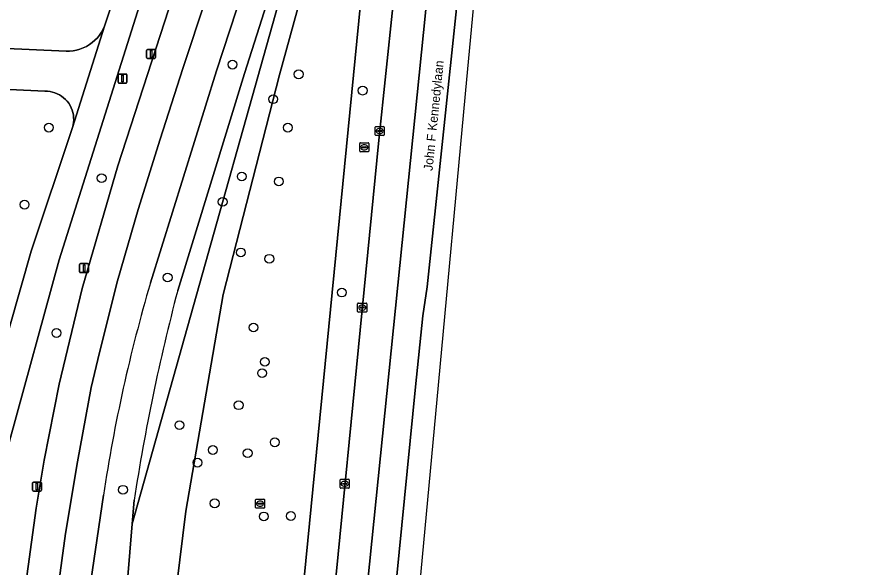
# Model space of a CAD drawing. Extents: x 161354 to 162026, y 386504 to 387460.
# Drawn here: x 161888.6 to 161983.7, y 386581.5 to 386642.5 of the extents above; entities that cross this region are included whole.
import ezdxf

# ---------------------------------------------------------------- set-up
doc = ezdxf.new("R2010")
doc.units = 0
for name, color, linetype in [('IMGEO_Berm_groen', 7, 'Continuous'), ('IMGEO_Boom', 7, 'Continuous'), ('IMGEO_Fietspad_gesloten', 7, 'Continuous'), ('IMGEO_Fietspad_open', 7, 'Continuous'), ('IMGEO_Groenvoorziening', 7, 'Continuous'), ('IMGEO_Kolk', 7, 'Continuous'), ('IMGEO_Lichtmast', 7, 'Continuous'), ('IMGEO_Loofbos', 7, 'Continuous'), ('IMGEO_Openbare_ruimte_label', 7, 'Continuous'), ('IMGEO_Rijbaan_regionaal_gesloten', 7, 'Continuous'), ('IMGEO_Rioolput', 7, 'Continuous'), ('IMGEO_Verkeersbordpaal', 7, 'Continuous')]:
    doc.layers.add(name, color=color, linetype=linetype)

msp = doc.modelspace()

# ---------------------------------------------------------------- linework, layer by layer
at = {"layer": 'IMGEO_Berm_groen'}
for points in [[(161934.511, 386701.688), (161935.18, 386707.852), (161935.602, 386701.48), (161931.177, 386682.181), (161926.052, 386665.823), (161928.732, 386665.815), (161932.494, 386665.803), (161936.118, 386700.366), (161937.946, 386716.259), (161935.283, 386716.755), (161932.789, 386707.078), (161930.115, 386698.021), (161925.994, 386683.412), (161910.651, 386636.523), (161903.327, 386613.063)], [(161923.643, 386665.83), (161926.052, 386665.823), (161931.177, 386682.181), (161935.602, 386701.48), (161935.18, 386707.852), (161934.511, 386701.688), (161928.819, 386682.727), (161921.08, 386659.304), (161913.742, 386636.257), (161906.341, 386612.212)], [(161906.341, 386612.212), (161913.742, 386636.257), (161921.08, 386659.304), (161928.819, 386682.727), (161934.511, 386701.688)], [(161901.521, 386589.008), (161901.303, 386586.383), (161923.643, 386665.83)], [(161898.125, 386589.557), (161896.34, 386577.532), (161895.193, 386564.876), (161893.103, 386537.735), (161892.934, 386535.989), (161898.185, 386535.127), (161902.766, 386534.908), (161902.789, 386535.354), (161903.229, 386539.182)], [(161899.074, 386555.691), (161899.477, 386564.438), (161899.737, 386567.556), (161901.303, 386586.383), (161901.521, 386589.008)]]:
    msp.add_lwpolyline(points, dxfattribs=at)
msp.add_lwpolyline([(161928.621, 386628.856), (161932.494, 386665.803), (161928.732, 386665.815), (161918.981, 386566.485), (161916.049, 386536.616), (161919.659, 386536.352), (161921.651, 386557.858)], close=True, dxfattribs=at)
for centre, radius, start, end in [((162069.828, 386563.887), 173.612, 163.54548, 171.49707), ((162122.974, 386555.11), 224.032, 165.2333, 171.29719), ((162122.974, 386555.11), 224.032, 165.2333, 171.29719)]:
    msp.add_arc(centre, radius, start, end, dxfattribs=at)
at = {"layer": 'IMGEO_Boom'}
for centre in [(161912.419, 386637.227), (161919.748, 386636.155), (161926.827, 386634.35), (161916.923, 386633.393), (161892.074, 386630.252), (161918.547, 386630.249), (161897.915, 386624.658), (161913.442, 386624.843), (161917.546, 386624.293), (161911.329, 386622.037), (161889.382, 386621.726), (161913.342, 386616.435), (161916.495, 386615.734), (161905.226, 386613.661), (161924.523, 386611.993), (161914.743, 386608.127), (161892.913, 386607.518), (161915.995, 386604.323), (161915.694, 386603.071), (161913.092, 386599.518), (161906.535, 386597.316), (161917.096, 386595.414), (161910.239, 386594.563), (161914.093, 386594.213), (161908.537, 386593.162), (161900.282, 386590.159), (161910.439, 386588.657), (161915.882, 386587.206), (161918.885, 386587.256)]:
    msp.add_circle(centre, 0.489, dxfattribs=at)
at = {"layer": 'IMGEO_Fietspad_gesloten'}
msp.add_lwpolyline([(161903.78, 386658.264), (161898.226, 386641.486), (161894.696, 386630.28), (161890.098, 386616.576), (161885.355, 386599.961), (161882.558, 386589.231), (161881.132, 386582.855), (161879.125, 386572.213), (161878.21, 386566.397), (161877.566, 386561.139), (161876.722, 386553.592), (161875.362, 386541.23), (161878.389, 386540.917), (161879.568, 386550.833), (161881.557, 386565.903), (161884.4, 386581.575), (161887.702, 386595.552), (161893.216, 386615.601), (161906.984, 386659.234)], dxfattribs=at)
at = {"layer": 'IMGEO_Fietspad_open'}
msp.add_lwpolyline([(161884.529, 386634.627), (161891.633, 386634.278), (161891.647, 386634.278), (161891.925, 386634.271), (161892.202, 386634.24), (161892.475, 386634.183), (161892.741, 386634.103), (161893, 386633.999), (161893.248, 386633.872), (161893.484, 386633.724), (161893.705, 386633.555), (161893.911, 386633.367), (161894.099, 386633.162), (161894.268, 386632.94), (161894.416, 386632.705), (161894.543, 386632.457), (161894.647, 386632.198), (161894.728, 386631.932), (161894.784, 386631.659), (161894.816, 386631.382), (161894.823, 386631.104), (161894.806, 386630.826), (161894.763, 386630.55), (161894.696, 386630.28), (161898.226, 386641.486), (161898.087, 386641.167), (161897.901, 386640.825), (161897.686, 386640.501), (161897.443, 386640.198), (161897.174, 386639.917), (161896.881, 386639.662), (161896.566, 386639.434), (161896.232, 386639.235), (161895.881, 386639.067), (161895.517, 386638.93), (161895.143, 386638.827), (161894.76, 386638.757), (161894.373, 386638.722), (161893.984, 386638.722), (161866.028, 386639.958)], dxfattribs=at)
at = {"layer": 'IMGEO_Groenvoorziening'}
for points in [[(161867.65, 386683.374), (161866.028, 386639.958), (161893.984, 386638.722), (161894.373, 386638.722), (161894.76, 386638.757), (161895.143, 386638.827), (161895.517, 386638.93), (161895.881, 386639.067), (161896.232, 386639.235), (161896.566, 386639.434), (161896.881, 386639.662), (161897.174, 386639.917), (161897.443, 386640.198), (161897.686, 386640.501), (161897.901, 386640.825), (161898.087, 386641.167), (161898.226, 386641.486), (161903.78, 386658.264)], [(161906.984, 386659.234), (161893.216, 386615.601), (161887.702, 386595.552), (161884.4, 386581.575), (161881.557, 386565.903), (161879.568, 386550.833), (161878.389, 386540.917), (161878.324, 386540.366), (161878.164, 386538.17)], [(161889.275, 386577.885), (161890.665, 386588.111), (161891.564, 386593.422), (161893.225, 386601.834), (161895.753, 386612.458), (161899.719, 386626.02), (161908.177, 386652.077), (161908.3, 386652.279)]]:
    msp.add_lwpolyline(points, dxfattribs=at)
for points in [[(161905.451, 386567.238), (161905.601, 386574.31), (161907.235, 386587.793), (161911.368, 386611.768), (161917.62, 386636.107), (161923.898, 386658.946), (161926.052, 386665.823), (161923.643, 386665.83), (161901.303, 386586.383), (161899.737, 386567.556)], [(161928.732, 386665.815), (161926.052, 386665.823), (161923.898, 386658.946), (161917.62, 386636.107), (161911.368, 386611.768), (161907.235, 386587.793), (161905.601, 386574.31), (161905.451, 386567.238), (161918.981, 386566.485)]]:
    msp.add_lwpolyline(points, close=True, dxfattribs=at)
at = {"layer": 'IMGEO_Kolk'}
for p, q in [((161928.223, 386629.45), (161928.223, 386630.302)), ((161928.298, 386630.376), (161929.15, 386630.376)), ((161928.525, 386629.919), (161928.923, 386629.919)), ((161928.711, 386630.156), (161928.736, 386630.156)), ((161929.224, 386630.302), (161929.224, 386629.45)), ((161929.15, 386629.376), (161928.298, 386629.376)), ((161928.482, 386629.87), (161928.482, 386629.882)), ((161928.92, 386629.833), (161928.522, 386629.833)), ((161928.734, 386629.596), (161928.709, 386629.596)), ((161928.966, 386629.882), (161928.966, 386629.87)), ((161926.278, 386609.9), (161926.278, 386610.752)), ((161926.353, 386610.826), (161927.205, 386610.826)), ((161926.537, 386610.32), (161926.537, 386610.332)), ((161926.975, 386610.283), (161926.577, 386610.283)), ((161926.58, 386610.369), (161926.978, 386610.369)), ((161926.789, 386610.046), (161926.764, 386610.046)), ((161926.766, 386610.606), (161926.791, 386610.606)), ((161927.021, 386610.332), (161927.021, 386610.32)), ((161927.279, 386610.752), (161927.279, 386609.9)), ((161927.205, 386609.826), (161926.353, 386609.826)), ((161924.349, 386590.397), (161924.349, 386591.249)), ((161924.424, 386591.323), (161925.276, 386591.323)), ((161924.837, 386591.103), (161924.862, 386591.103)), ((161925.35, 386591.249), (161925.35, 386590.397)), ((161925.276, 386590.323), (161924.424, 386590.323)), ((161924.608, 386590.817), (161924.608, 386590.829)), ((161925.046, 386590.78), (161924.648, 386590.78)), ((161924.651, 386590.866), (161925.049, 386590.866)), ((161924.86, 386590.543), (161924.835, 386590.543)), ((161925.092, 386590.829), (161925.092, 386590.817))]:
    msp.add_line(p, q, dxfattribs=at)
for points in [[(161928.223, 386629.45), (161928.223, 386630.302)], [(161928.298, 386630.376), (161929.15, 386630.376)], [(161929.224, 386630.302), (161929.224, 386629.45)], [(161929.15, 386629.376), (161928.298, 386629.376)], [(161926.278, 386609.9), (161926.278, 386610.752)], [(161926.353, 386610.826), (161927.205, 386610.826)], [(161927.279, 386610.752), (161927.279, 386609.9)], [(161927.205, 386609.826), (161926.353, 386609.826)], [(161924.349, 386590.397), (161924.349, 386591.249)], [(161924.424, 386591.323), (161925.276, 386591.323)], [(161925.35, 386591.249), (161925.35, 386590.397)], [(161925.276, 386590.323), (161924.424, 386590.323)]]:
    msp.add_lwpolyline(points, dxfattribs=at)
for centre, radius, start, end in [((161928.3, 386630.3), 0.0765, 91.55205, 178.44795), ((161928.3, 386630.3), 0.0765, 91.55205, 178.44795), ((161928.522, 386629.879), 0.0403, 85.87752, 175.75265), ((161928.927, 386629.881), 0.0386, 1.73085, 96.63898), ((161929.148, 386630.3), 0.0765, 1.55205, 88.44795), ((161929.148, 386630.3), 0.0765, 1.55205, 88.44795), ((161928.3, 386629.452), 0.0765, 181.55205, 268.44795), ((161928.3, 386629.452), 0.0765, 181.55205, 268.44795), ((161928.519, 386629.869), 0.0366, 178.93798, 274.71019), ((161928.923, 386629.876), 0.043, 264.86636, 352.45326), ((161929.148, 386629.452), 0.0765, 271.55205, 358.44795), ((161929.148, 386629.452), 0.0765, 271.55205, 358.44795), ((161926.355, 386610.75), 0.0765, 91.55205, 178.44795), ((161926.355, 386610.75), 0.0765, 91.55205, 178.44795), ((161926.577, 386610.329), 0.0403, 85.87752, 175.75265), ((161926.574, 386610.319), 0.0366, 178.93798, 274.71019), ((161926.978, 386610.326), 0.043, 264.86636, 352.45326), ((161926.982, 386610.331), 0.0386, 1.73085, 96.63898), ((161927.203, 386610.75), 0.0765, 1.55205, 88.44795), ((161927.203, 386610.75), 0.0765, 1.55205, 88.44795), ((161926.355, 386609.902), 0.0765, 181.55205, 268.44795), ((161926.355, 386609.902), 0.0765, 181.55205, 268.44795), ((161927.203, 386609.902), 0.0765, 271.55205, 358.44795), ((161927.203, 386609.902), 0.0765, 271.55205, 358.44795), ((161924.426, 386591.247), 0.0765, 91.55205, 178.44795), ((161924.426, 386591.247), 0.0765, 91.55205, 178.44795), ((161925.274, 386591.247), 0.0765, 1.55205, 88.44795), ((161925.274, 386591.247), 0.0765, 1.55205, 88.44795), ((161924.426, 386590.399), 0.0765, 181.55205, 268.44795), ((161924.426, 386590.399), 0.0765, 181.55205, 268.44795), ((161924.648, 386590.826), 0.0403, 85.87752, 175.75265), ((161924.645, 386590.816), 0.0366, 178.93798, 274.71019), ((161925.049, 386590.823), 0.043, 264.86636, 352.45326), ((161925.053, 386590.828), 0.0386, 1.73085, 96.63898), ((161925.274, 386590.399), 0.0765, 271.55205, 358.44795), ((161925.274, 386590.399), 0.0765, 271.55205, 358.44795)]:
    msp.add_arc(centre, radius, start, end, dxfattribs=at)
for centre, major_axis, ratio, start_param, end_param in [((161928.71, 386629.876), (-0.387, 0.002), 0.722429, 4.712389, 7.853982), ((161928.735, 386629.876), (-0.39, 0.002), 0.717154, 1.570796, 4.712389), ((161926.765, 386610.326), (-0.387, 0.002), 0.722429, 4.712389, 7.853982), ((161926.79, 386610.326), (-0.39, 0.002), 0.717154, 1.570796, 4.712389), ((161924.836, 386590.823), (-0.387, 0.002), 0.722429, 4.712389, 7.853982), ((161924.861, 386590.823), (-0.39, 0.002), 0.717154, 1.570796, 4.712389)]:
    msp.add_ellipse(centre, major_axis=major_axis, ratio=ratio, start_param=start_param, end_param=end_param, dxfattribs=at)
at = {"layer": 'IMGEO_Lichtmast'}
for p, q in [((161902.906, 386637.995), (161902.906, 386638.795)), ((161902.906, 386638.795), (161902.906, 386637.995)), ((161903.006, 386638.895), (161903.796, 386638.895)), ((161903.796, 386638.895), (161903.006, 386638.895)), ((161903.896, 386638.795), (161903.896, 386637.995)), ((161903.896, 386637.995), (161903.896, 386638.795)), ((161903.796, 386637.895), (161903.006, 386637.895)), ((161903.006, 386637.895), (161903.796, 386637.895)), ((161895.479, 386614.296), (161895.479, 386615.096)), ((161895.479, 386615.096), (161895.479, 386614.296)), ((161895.579, 386615.196), (161896.369, 386615.196)), ((161896.369, 386615.196), (161895.579, 386615.196)), ((161896.469, 386615.096), (161896.469, 386614.296)), ((161896.469, 386614.296), (161896.469, 386615.096)), ((161896.369, 386614.196), (161895.579, 386614.196)), ((161895.579, 386614.196), (161896.369, 386614.196)), ((161890.263, 386590.111), (161890.263, 386590.911)), ((161890.263, 386590.911), (161890.263, 386590.111)), ((161890.363, 386591.011), (161891.153, 386591.011)), ((161891.153, 386591.011), (161890.363, 386591.011)), ((161891.253, 386590.911), (161891.253, 386590.111)), ((161891.253, 386590.111), (161891.253, 386590.911)), ((161891.153, 386590.011), (161890.363, 386590.011)), ((161890.363, 386590.011), (161891.153, 386590.011))]:
    msp.add_line(p, q, dxfattribs=at)
for points in [[(161903.326, 386638.77), (161903.476, 386638.77), (161903.476, 386638.02), (161903.326, 386638.02), (161903.326, 386638.77)], [(161895.899, 386615.071), (161896.049, 386615.071), (161896.049, 386614.321), (161895.899, 386614.321), (161895.899, 386615.071)], [(161890.683, 386590.886), (161890.833, 386590.886), (161890.833, 386590.136), (161890.683, 386590.136), (161890.683, 386590.886)]]:
    msp.add_lwpolyline(points, dxfattribs=at)
for centre, start, end in [((161903.006, 386638.795), 90, 180), ((161903.006, 386638.795), 90, 180), ((161903.796, 386638.795), 0, 90), ((161903.796, 386638.795), 360, 90), ((161903.006, 386637.995), 180, 270), ((161903.006, 386637.995), 180, 270), ((161903.796, 386637.995), 270, 0), ((161903.796, 386637.995), 270, 0), ((161895.579, 386615.096), 90, 180), ((161895.579, 386615.096), 90, 180), ((161896.369, 386615.096), 0, 90), ((161896.369, 386615.096), 360, 90), ((161895.579, 386614.296), 180, 270), ((161895.579, 386614.296), 180, 270), ((161896.369, 386614.296), 270, 0), ((161896.369, 386614.296), 270, 0), ((161890.363, 386590.911), 90, 180), ((161890.363, 386590.911), 90, 180), ((161891.153, 386590.911), 0, 90), ((161891.153, 386590.911), 360, 90), ((161890.363, 386590.111), 180, 270), ((161890.363, 386590.111), 180, 270), ((161891.153, 386590.111), 270, 0), ((161891.153, 386590.111), 270, 0)]:
    msp.add_arc(centre, 0.1, start, end, dxfattribs=at)
at = {"layer": 'IMGEO_Loofbos'}
msp.add_lwpolyline([(161885.355, 386599.961), (161890.098, 386616.576), (161894.696, 386630.28), (161894.763, 386630.55), (161894.806, 386630.826), (161894.823, 386631.104), (161894.816, 386631.382), (161894.784, 386631.659), (161894.728, 386631.932), (161894.647, 386632.198), (161894.543, 386632.457), (161894.416, 386632.705), (161894.268, 386632.94), (161894.099, 386633.162), (161893.911, 386633.367), (161893.705, 386633.555), (161893.484, 386633.724), (161893.248, 386633.872), (161893, 386633.999), (161892.741, 386634.103), (161892.475, 386634.183), (161892.202, 386634.24), (161891.925, 386634.271), (161891.647, 386634.278), (161891.633, 386634.278), (161884.529, 386634.627)], dxfattribs=at)
at = {"layer": 'IMGEO_Rijbaan_regionaal_gesloten'}
for points in [[(161953.318, 386794.679), (161962.379, 386873.244), (161976.049, 386997.238), (161981.984, 387049.448), (161978.469, 387049.798), (161974.354, 387011.236), (161973.137, 387000.209), (161967.661, 386954.866), (161949.872, 386795.06), (161946.557, 386765.215), (161942.589, 386729.489), (161942.439, 386728.019), (161926.424, 386570.316), (161923.246, 386535.823), (161922.934, 386532.145), (161926.119, 386532.024), (161929.934, 386573.912), (161932.687, 386601.55), (161933.498, 386609.431), (161933.982, 386612.625), (161940.783, 386677.087)], [(161928.749, 386531.924), (161935.094, 386600.16), (161938.388, 386635.586), (161940.62, 386659.585), (161959.612, 386832.977), (161983.673, 387049.28), (161981.984, 387049.448), (161976.049, 386997.238), (161962.379, 386873.244), (161953.318, 386794.679), (161940.783, 386677.087), (161933.982, 386612.625), (161933.498, 386609.431), (161932.687, 386601.55), (161929.934, 386573.912), (161926.119, 386532.024)]]:
    msp.add_lwpolyline(points, close=True, dxfattribs=at)
for points in [[(161903.327, 386613.063), (161910.651, 386636.523), (161925.994, 386683.412), (161930.115, 386698.021), (161932.789, 386707.078), (161935.283, 386716.755), (161935.67, 386718.254), (161938.296, 386728.443)], [(161939.327, 386728.264), (161938.117, 386717.747), (161937.946, 386716.259), (161936.118, 386700.366), (161932.494, 386665.803), (161928.621, 386628.856), (161921.651, 386557.858), (161919.659, 386536.352), (161919.282, 386532.283), (161922.934, 386532.145), (161923.246, 386535.823), (161926.424, 386570.316), (161942.439, 386728.019)], [(161912.122, 386652.517), (161906.922, 386636.787), (161904.417, 386628.989), (161901.969, 386621.172), (161899.677, 386613.308), (161897.675, 386605.366), (161896.776, 386601.482), (161895.228, 386593.238), (161893.917, 386585.307), (161892.8, 386577.15), (161891.613, 386564.816), (161890.938, 386556.75), (161889.832, 386542.31), (161889.41, 386536.784), (161885.766, 386537.53)], [(161908.177, 386652.077), (161899.719, 386626.02), (161895.753, 386612.458), (161893.225, 386601.834), (161891.564, 386593.422), (161890.665, 386588.111), (161889.275, 386577.885), (161886.699, 386547.139), (161886.174, 386540.45), (161885.766, 386537.53), (161889.41, 386536.784), (161889.832, 386542.31), (161890.938, 386556.75), (161891.613, 386564.816), (161892.8, 386577.15), (161893.917, 386585.307), (161895.228, 386593.238), (161896.776, 386601.482), (161897.675, 386605.366), (161899.677, 386613.308), (161901.969, 386621.172), (161904.417, 386628.989), (161906.922, 386636.787), (161912.122, 386652.517)], [(161880.967, 386530.646), (161892.474, 386529.177), (161892.725, 386532.656), (161892.934, 386535.989), (161893.103, 386537.735), (161895.193, 386564.876), (161896.34, 386577.532), (161898.125, 386589.557)]]:
    msp.add_lwpolyline(points, dxfattribs=at)
msp.add_arc((162069.828, 386563.887), 173.612, 163.54548, 171.49707, dxfattribs=at)
at = {"layer": 'IMGEO_Rioolput'}
for p, q in [((161926.501, 386627.645), (161926.501, 386628.497)), ((161926.576, 386628.571), (161927.428, 386628.571)), ((161926.76, 386628.065), (161926.76, 386628.077)), ((161927.198, 386628.028), (161926.8, 386628.028)), ((161926.803, 386628.114), (161927.201, 386628.114)), ((161926.989, 386628.351), (161927.014, 386628.351)), ((161927.244, 386628.077), (161927.244, 386628.065)), ((161927.502, 386628.497), (161927.502, 386627.645)), ((161927.428, 386627.571), (161926.576, 386627.571)), ((161927.012, 386627.791), (161926.987, 386627.791)), ((161914.976, 386588.196), (161914.976, 386589.048)), ((161915.051, 386589.122), (161915.903, 386589.122)), ((161915.977, 386589.048), (161915.977, 386588.196)), ((161915.903, 386588.122), (161915.051, 386588.122)), ((161915.235, 386588.616), (161915.235, 386588.628)), ((161915.673, 386588.579), (161915.275, 386588.579)), ((161915.278, 386588.665), (161915.676, 386588.665)), ((161915.487, 386588.342), (161915.462, 386588.342)), ((161915.464, 386588.902), (161915.489, 386588.902)), ((161915.719, 386588.628), (161915.719, 386588.616))]:
    msp.add_line(p, q, dxfattribs=at)
for points in [[(161926.501, 386627.645), (161926.501, 386628.497)], [(161926.576, 386628.571), (161927.428, 386628.571)], [(161927.502, 386628.497), (161927.502, 386627.645)], [(161927.428, 386627.571), (161926.576, 386627.571)], [(161914.976, 386588.196), (161914.976, 386589.048)], [(161915.051, 386589.122), (161915.903, 386589.122)], [(161915.977, 386589.048), (161915.977, 386588.196)], [(161915.903, 386588.122), (161915.051, 386588.122)]]:
    msp.add_lwpolyline(points, dxfattribs=at)
for centre, radius, start, end in [((161926.578, 386628.495), 0.0765, 91.55205, 178.44795), ((161926.578, 386628.495), 0.0765, 91.55205, 178.44795), ((161926.8, 386628.074), 0.0403, 85.87752, 175.75265), ((161926.797, 386628.064), 0.0366, 178.93798, 274.71019), ((161927.201, 386628.071), 0.043, 264.86636, 352.45326), ((161927.205, 386628.076), 0.0386, 1.73085, 96.63898), ((161927.426, 386628.495), 0.0765, 1.55205, 88.44795), ((161927.426, 386628.495), 0.0765, 1.55205, 88.44795), ((161926.578, 386627.647), 0.0765, 181.55205, 268.44795), ((161926.578, 386627.647), 0.0765, 181.55205, 268.44795), ((161927.426, 386627.647), 0.0765, 271.55205, 358.44795), ((161927.426, 386627.647), 0.0765, 271.55205, 358.44795), ((161915.053, 386589.046), 0.0765, 91.55205, 178.44795), ((161915.053, 386589.046), 0.0765, 91.55205, 178.44795), ((161915.901, 386589.046), 0.0765, 1.55205, 88.44795), ((161915.901, 386589.046), 0.0765, 1.55205, 88.44795), ((161915.053, 386588.198), 0.0765, 181.55205, 268.44795), ((161915.053, 386588.198), 0.0765, 181.55205, 268.44795), ((161915.275, 386588.625), 0.0403, 85.87752, 175.75265), ((161915.272, 386588.615), 0.0366, 178.93798, 274.71019), ((161915.676, 386588.622), 0.043, 264.86636, 352.45326), ((161915.68, 386588.627), 0.0386, 1.73085, 96.63898), ((161915.901, 386588.198), 0.0765, 271.55205, 358.44795), ((161915.901, 386588.198), 0.0765, 271.55205, 358.44795)]:
    msp.add_arc(centre, radius, start, end, dxfattribs=at)
for centre, major_axis, ratio, start_param, end_param in [((161926.988, 386628.071), (-0.387, 0.002), 0.722429, 4.712389, 7.853982), ((161927.013, 386628.071), (-0.39, 0.002), 0.717154, 1.570796, 4.712389), ((161915.463, 386588.622), (-0.387, 0.002), 0.722429, 4.712389, 7.853982), ((161915.488, 386588.622), (-0.39, 0.002), 0.717154, 1.570796, 4.712389)]:
    msp.add_ellipse(centre, major_axis=major_axis, ratio=ratio, start_param=start_param, end_param=end_param, dxfattribs=at)
at = {"layer": 'IMGEO_Verkeersbordpaal'}
for p, q in [((161899.737, 386635.284), (161899.737, 386636.084)), ((161899.737, 386636.084), (161899.737, 386635.284)), ((161899.837, 386636.184), (161900.627, 386636.184)), ((161900.627, 386636.184), (161899.837, 386636.184)), ((161900.727, 386636.084), (161900.727, 386635.284)), ((161900.727, 386635.284), (161900.727, 386636.084)), ((161900.627, 386635.184), (161899.837, 386635.184)), ((161899.837, 386635.184), (161900.627, 386635.184))]:
    msp.add_line(p, q, dxfattribs=at)
msp.add_lwpolyline([(161900.157, 386636.059), (161900.307, 386636.059), (161900.307, 386635.309), (161900.157, 386635.309), (161900.157, 386636.059)], dxfattribs=at)
for centre, start, end in [((161899.837, 386636.084), 90, 180), ((161899.837, 386636.084), 90, 180), ((161900.627, 386636.084), 0, 90), ((161900.627, 386636.084), 360, 90), ((161899.837, 386635.284), 180, 270), ((161899.837, 386635.284), 180, 270), ((161900.627, 386635.284), 270, 0), ((161900.627, 386635.284), 270, 0)]:
    msp.add_arc(centre, 0.1, start, end, dxfattribs=at)

# ---------------------------------------------------------------- texts
at = {"layer": 'IMGEO_Openbare_ruimte_label'}
msp.add_text('John F Kennedylaan', height=1, rotation=84.08993, dxfattribs=at).set_placement((161934.563, 386625.432))

doc.saveas('drawing.dxf')
